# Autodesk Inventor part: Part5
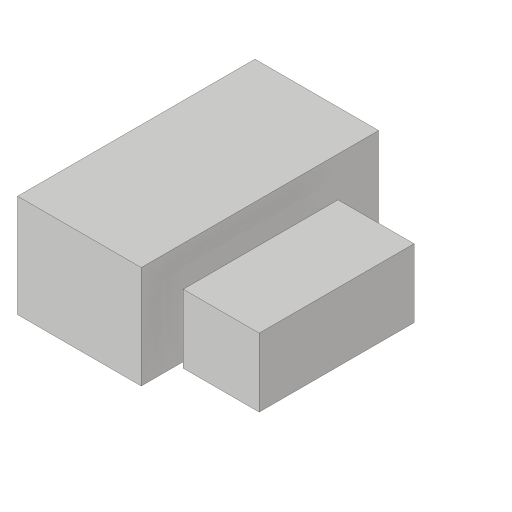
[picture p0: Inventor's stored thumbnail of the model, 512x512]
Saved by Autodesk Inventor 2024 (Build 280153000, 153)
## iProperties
Created: 2015-07
Part Number: Part5
Material: Generic
Document SubType Name: Modeling
Designer: Sandeep
Density: 1 g/cm^3
Appearance: Default
Author: Sandeep
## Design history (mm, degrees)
sketch "Sketch1"
  geometry: L1 (-7.411, 3.941)-(-1.385, 3.941); L2 (-1.385, 3.941)-(-1.385, -7.628); L3 (-1.385, -7.628)-(-7.411, -7.628); L4 (-7.411, -7.628)-(-7.411, 3.941); 1 further point
  constraints: 8 end point, 2 parallel, 1 horizontal, 1 perpendicular
extrude "Extrusion1" new body sketch "Sketch1" distance "d0" = 5; taper "d1" = 0 deg
sketch "Sketch2"
  geometry: L1 (1.52, -7.467)-(7.078, -7.467); L2 (7.078, -7.467)-(7.078, 3.854); L3 (7.078, 3.854)-(1.52, 3.854); L4 (1.52, 3.854)-(1.52, -7.467); 1 further point
  constraints: 8 end point, 2 parallel, 1 horizontal, 1 perpendicular
extrude "Extrusion2" new body sketch "Sketch2" distance "d2" = 5; taper "d3" = 0 deg
node "Direct Edit1"
body "Solid1"
body "Solid2"
feature "Scale1"
other parameters: "d4" = 15
